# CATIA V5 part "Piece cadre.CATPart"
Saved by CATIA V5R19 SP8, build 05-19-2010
Part number: Piece cadre
Bounding box of the stored display mesh (mm): x -1.383 to 50.762, y 0.217 to 66.442, z -7.478 to 7.478
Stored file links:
  G:\EU_thinkMotion\CFAO_2010\MMS_groupe3\MMS_groupe3\A reprendre\lpastor\lpastor\Piece cadre.CATPart
  C:\Users\Loïc\Documents\IFMA\Cours 2A\CFAO\Thinkmotion\Fourche avant.CATProduct
  G:\EU_thinkMotion\CFAO_2010\MMS_groupe3\MMS_groupe3\A reprendre\lpastor\lpastor\Pieces.CATProduct
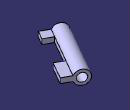
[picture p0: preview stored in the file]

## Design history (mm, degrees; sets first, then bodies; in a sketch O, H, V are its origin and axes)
External parameters (linked from other documents)
  External.Parametre_rayon_exterieur_tube_cadre = 0.0075
  External.Parametre_rayon_interieur_tube_cadre = 0.0045
Set1
  Plane1: linked copy from another document
  Line1 "Droite AB (cadre)": linked copy from another document
  Plane2: linked copy from another document
Body1 (main body)
  Sketch1 on Plane1, origin (36.0149, 62.7953, 0), H (0.8675, -0.4975, 0), V (0, 0, 1)
    arc A1 centre (0, 0) radius 7.5 from (7, 2.6926) to (7, -2.6926) ccw
    circle A2 centre (0, 0) radius 4.5
    point P2 (0, 0)
    reference projected point E1 (0, 0) from Line1
    line L1 (7, -2.6926) -> (7, 2.6926)
    radius A2 = 4.5 {= External.Parametre_rayon_interieur_tube_cadre}
    radius A1 = 7.5 {= External.Parametre_rayon_exterieur_tube_cadre}
    distance A1 L1 = 0.5
    concentricity: A2 A1
    coincidence: P2 E1
    vertical: L1 V
  Pad1: profile Sketch1, direction (-0.4975, -0.8675, 0), up to Plane2
  Sketch2 on face of Pad1 from Sketch1.L1, origin (6.0722, -3.4826, 0), H (0.4975, 0.8675, 0), V (0, 0, 1)
    line L1 (52.3901, 2.6926) -> (72.3901, 2.6926)
    line L2 (72.3901, 2.6926) -> (72.3901, -2.6926)
    line L3 (72.3901, -2.6926) -> (52.3901, -2.6926)
    line L4 (52.3901, -2.6926) -> (52.3901, 2.6926)
    reference projected line E1 (72.3901, 2.6926) -> (10, 2.6926) from edge [face of Pad1 from Sketch1.A1 | face of Pad1 from Sketch1.L1]
    reference projected line E2 (72.3901, -2.6926) -> (10, -2.6926) from edge [face of Pad1 from Sketch1.L1 | face of Pad1 from Sketch1.A1]
    reference projected line E3 (72.3901, -2.6926) -> (72.3901, 2.6926) from edge [start face of Pad1 | face of Pad1 from Sketch1.L1]
    line L5 (10, 2.6926) -> (20, 2.6926)
    line L6 (20, 2.6926) -> (20, -2.6926)
    line L7 (20, -2.6926) -> (10, -2.6926)
    line L8 (10, -2.6926) -> (10, 2.6926)
    reference projected line E4 (72.3901, -2.6926) -> (10, -2.6926) from edge [face of Pad1 from Sketch1.L1 | face of Pad1 from Sketch1.A1]
    reference projected line E5 (72.3901, 2.6926) -> (10, 2.6926) from edge [face of Pad1 from Sketch1.A1 | face of Pad1 from Sketch1.L1]
    reference projected line E6 (10, 2.6926) -> (10, -2.6926) from edge [end face of Pad1 | face of Pad1 from Sketch1.L1]
    distance L4 L2 = 20
    distance L6 L8 = 10
    horizontal: L1 H, L3 H, L5 H, L7 H
    vertical: L2 V, L4 V, L6 V, L8 V
    coincidence: L1 E1, L3 E2, L2 E3, L7 E4, L5 E5, L8 E6
  Pad2: profile Sketch2, direction (0.8675, -0.4975, 0), length 10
